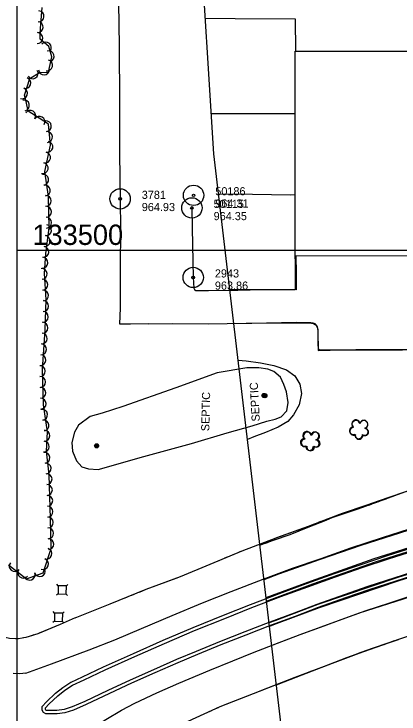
# Model space of a CAD drawing. Extents: x 353423 to 364002, y 127000 to 201942.
# Drawn here: x 359998 to 360282, y 133158 to 133674 of the extents above; entities that cross this region are included whole.
import ezdxf

# ---------------------------------------------------------------- set-up
doc = ezdxf.new("R2010")
doc.units = 0
for name, color, linetype in [('E_DTM_SlopeTop', 7, 'Continuous'), ('E_FEN_Generic', 7, 'Continuous'), ('E_LAND_TreeLine', 7, 'Continuous'), ('E_MISCPROP', 7, 'Continuous'), ('E_RDWY_AsphConc', 7, 'Continuous'), ('E_RDWY_Gravel', 7, 'Continuous'), ('E_SGN', 7, 'Continuous'), ('E_STRUCT_WingWall', 7, 'Continuous'), ('E_UTL_ETransformer', 7, 'Continuous'), ('E_WTR_FlowLine', 7, 'Continuous')]:
    doc.layers.add(name, color=color, linetype=linetype)

msp = doc.modelspace()

# ---------------------------------------------------------------- linework, layer by layer
at = {"layer": 'E_DTM_SlopeTop'}
for points in [[(360182.12, 133256.96), (360192.85, 133261.23), (360223.69, 133272.01), (360253.77, 133282.21), (360288.47, 133293.44), (360326.84, 133305.23), (360357.9, 133313.97), (360390.26, 133322.54), (360421.44, 133330.15), (360456.51, 133337.86), (360490.45, 133344.97), (360520.11, 133351.38), (360526.85, 133354.04), (360530.53, 133357.19), (360539.85, 133363.92), (360547.02, 133368.71), (360550.06, 133372.44), (360551.65, 133376.4), (360553.23, 133383.39), (360555.89, 133430.41), (360555.81, 133481.76), (360555.33, 133565.87), (360555.51, 133660.84), (360555.37, 133755.07)], [(360128.86, 133531.05), (360129.08, 133516.28), (360129.63, 133491.43), (360129.78, 133479.76), (360130.16, 133471.75), (360130.71, 133470.77), (360131.62, 133470.21), (360141.06, 133470.2), (360162.72, 133470.44), (360181.1, 133470.82), (360204.94, 133471.01), (360205.25, 133471.93), (360205.33, 133481.18), (360205.17, 133491.08), (360205.14, 133495.5)], [(360006.29, 133187.84), (360025.26, 133194.79), (360052.98, 133205.1), (360071.85, 133212.44), (360091.53, 133220.77), (360114.27, 133230.3), (360136.54, 133239.67), (360157.72, 133248.11), (360181.38, 133257.23), (360202.94, 133265.29), (360224.09, 133272.51), (360246, 133280.32), (360269.41, 133287.87), (360289.47, 133294.36), (360314.09, 133301.78), (360333.1, 133307.44), (360354.51, 133313.55), (360373.78, 133318.45), (360400.17, 133325.29), (360427.85, 133331.85), (360453.76, 133337.85), (360478.53, 133342.83), (360499.94, 133347.22), (360523.7, 133352.98)], [(360589.7, 133314.3), (360545.54, 133307.42), (360507.24, 133300.53), (360457.59, 133289.96), (360418.36, 133280.97), (360373.04, 133269.25), (360336.05, 133258.69), (360290.01, 133244.21), (360252.17, 133232.01), (360208.39, 133216.08), (360187.87, 133208.16)], [(360183.69, 133243.58), (360217.12, 133255.99), (360263.43, 133272.4), (360311.1, 133287.46)], [(360183.99, 133241.03), (360217.97, 133253.64), (360264.23, 133270.03), (360311.83, 133285.06)], [(360048.16, 133185.18), (360063.68, 133192.49), (360085.62, 133202.44), (360107.65, 133212.12), (360129.82, 133221.52), (360152.13, 133230.53), (360172.18, 133238.56), (360193.58, 133246.71), (360213.43, 133253.97), (360233.99, 133261.3), (360253.68, 133268.06), (360273.18, 133274.61), (360287.89, 133279.27)], [(360049.22, 133182.92), (360064.73, 133190.22), (360086.64, 133200.16), (360108.64, 133209.83), (360130.77, 133219.21), (360153.06, 133228.21), (360173.09, 133236.23), (360194.46, 133244.37), (360214.28, 133251.62), (360234.82, 133258.94), (360254.48, 133265.69), (360273.95, 133272.23), (360288.64, 133276.88)], [(360338.92, 133276.37), (360280.78, 133258.43), (360221.84, 133238.4), (360190.01, 133226.54), (360185.89, 133224.91)], [(360339.61, 133273.97), (360281.55, 133256.05), (360222.68, 133236.05), (360190.9, 133224.2), (360186.2, 133222.34)], [(360297.01, 133261.39), (360279.3, 133255.81), (360259.36, 133249.41), (360242.08, 133243.3), (360221.97, 133236.19), (360205.07, 133229.68), (360187.2, 133223.2), (360168.68, 133215.98), (360150.18, 133208.68), (360132.89, 133201.57), (360118.38, 133195.54), (360101.55, 133188.14), (360084.2, 133180.38), (360067.91, 133172.85), (360050.88, 133164.62), (360041.39, 133160.54), (360035.04, 133158.61), (360029.37, 133157.92), (360022.49, 133157.84), (360021.01, 133157.88), (360019.2, 133158.79), (360018.29, 133160.45), (360018.36, 133163.29), (360021.5, 133166.62), (360028.28, 133173.1), (360033.56, 133177.33), (360039.45, 133181.1)], [(360296.26, 133263.78), (360278.54, 133258.2), (360258.56, 133251.78), (360241.25, 133245.66), (360221.1, 133238.54), (360204.2, 133232.03), (360186.32, 133225.54), (360167.77, 133218.31), (360149.24, 133211), (360131.94, 133203.88), (360117.4, 133197.84), (360100.53, 133190.42), (360083.16, 133182.66), (360066.85, 133175.11), (360049.84, 133166.89), (360040.53, 133162.89), (360034.53, 133161.07), (360029.2, 133160.42), (360022.51, 133160.34), (360021.63, 133160.36), (360021.02, 133160.67), (360020.81, 133161.06), (360020.84, 133162.27), (360023.28, 133164.86), (360029.92, 133171.22), (360035.02, 133175.3), (360040.79, 133179)], [(360076.88, 133160.45), (360086.72, 133165.72), (360102.95, 133173.41), (360119.06, 133180.57), (360141.94, 133190.03), (360159.08, 133196.98), (360174.81, 133203.33), (360191.95, 133209.89), (360208.75, 133216.28), (360223.61, 133221.86), (360239.68, 133227.59), (360257.45, 133233.96), (360274.1, 133239.6), (360292.65, 133245.74)], [(360006.29, 133187.84), (360001.88, 133187.31), (359997.03, 133187.56)], [(360039.66, 133181.22), (360048.16, 133185.19)], [(360040.71, 133178.95), (360049.22, 133182.92)], [(360048.78, 132621.5), (360048.89, 132669.64), (360049.35, 132727.67), (360049.55, 132793.59), (360049.56, 132842.31), (360049.06, 132893.44), (360046.96, 132939.69), (360042.98, 132986.33), (360039.67, 133020.54), (360037.17, 133037.76), (360034.31, 133052.24), (360029.63, 133066.98), (360021.41, 133087.08), (360018.16, 133096.99), (360017.7, 133101.52), (360017.78, 133107.23), (360018.75, 133112.13), (360021.8, 133117.95), (360028.18, 133126.37), (360033.76, 133132.81), (360043.26, 133140.02), (360051.73, 133145.18), (360065.4, 133153.61), (360076.88, 133160.45)]]:
    msp.add_lwpolyline(points, dxfattribs=at)
at = {"layer": 'E_FEN_Generic'}
for points in [[(360023.51, 133516.3), (360023.03, 133539.52), (360020.34, 133557.82), (360024.58, 133577.27), (360023.05, 133592.9), (360016.13, 133597.27), (360007.97, 133602.47), (360006.49, 133609.49), (360005.25, 133614.26), (360009.3, 133626.61), (360016.25, 133630.93), (360023.1, 133631.24), (360025.57, 133642.42), (360023.26, 133650.2), (360016.84, 133655.65), (360017.12, 133663.42), (360018.26, 133679.03)], [(359993.54, 133267.74), (360006.67, 133257.42), (360018.96, 133261.79), (360025.04, 133279.74), (360024.57, 133301.97), (360023.6, 133334.04), (360021.52, 133351.55), (360022.19, 133365.95), (360019.31, 133385.68), (360018.66, 133411.81), (360020.6, 133441.03), (360021.33, 133463.41), (360020.05, 133482.68), (360021.15, 133497.42), (360023.51, 133516.29)]]:
    msp.add_lwpolyline(points, dxfattribs=at)
for centre, radius, start, end in [((360015.68, 133672.43), 4, 265.8265, 85.8112), ((360015.1, 133664.45), 4, 265.8265, 85.8112), ((360014.77, 133656.38), 4, 267.9556, 87.9403), ((360021.08, 133649.3), 4, 319.6336, 139.6183), ((360023.22, 133642.97), 4, 286.559, 106.5437), ((360022.06, 133636.22), 4, 257.5917, 77.5764), ((360011.33, 133630.33), 4, 211.8706, 31.8553), ((360019.66, 133633.18), 4, 182.5959, 2.5806), ((360005.97, 133623.16), 4, 251.8341, 71.8188), ((360003.48, 133615.56), 4, 251.8341, 71.8188), ((360004.93, 133606.72), 4, 281.898, 101.8827), ((360009.55, 133598.98), 4, 327.4836, 147.4683), ((360016.31, 133594.68), 4, 327.7358, 147.7205), ((360021.1, 133591.35), 4, 275.6048, 95.5895), ((360021.88, 133583.39), 4, 275.6048, 95.5895), ((360022.19, 133576.11), 4, 257.6917, 77.6764), ((360020.48, 133568.3), 4, 257.6917, 77.6764), ((360018.77, 133560.48), 4, 257.6917, 77.6764), ((360019.1, 133551.85), 4, 278.3724, 98.357), ((360020.26, 133543.93), 4, 278.3724, 98.357), ((360021, 133536.25), 4, 271.1997, 91.1844), ((360021.17, 133528.25), 4, 271.1997, 91.1844), ((360021.33, 133520.25), 4, 271.1997, 91.1844), ((360021.19, 133514.63), 4, 262.8788, 82.8634), ((360020.2, 133506.69), 4, 262.8788, 82.8634), ((360019.21, 133498.75), 4, 262.8788, 82.8634), ((360018.55, 133490.68), 4, 265.7322, 85.7169), ((360017.97, 133482.41), 4, 273.806, 93.7907), ((360018.5, 133474.43), 4, 273.806, 93.7907), ((360019.03, 133466.44), 4, 273.806, 93.7907), ((360019.08, 133458.66), 4, 268.1534, 88.1381), ((360018.82, 133450.67), 4, 268.1534, 88.1381), ((360018.56, 133442.67), 4, 268.1534, 88.1381), ((360018.09, 133434.76), 4, 266.2005, 86.1852), ((360017.56, 133426.78), 4, 266.2005, 86.1852), ((360017.03, 133418.8), 4, 266.2005, 86.1852), ((360016.59, 133410.62), 4, 271.4384, 91.423), ((360016.79, 133402.62), 4, 271.4384, 91.423), ((360016.99, 133394.63), 4, 271.4384, 91.423), ((360017.19, 133386.63), 4, 271.4384, 91.423), ((360018.25, 133378.46), 4, 278.3235, 98.3082), ((360019.41, 133370.54), 4, 278.3235, 98.3082), ((360249.85, 133371.69), 2.97, 7.0637, 228.2976), ((360249.92, 133371.25), 2.97, 8.7472, 229.9811), ((360255.7, 133371.44), 2.97, 284.7145, 167.6878), ((360255.78, 133371.17), 2.97, 286.3981, 169.3713), ((360247.87, 133366.69), 2.78, 90.0346, 297.8076), ((360248.09, 133366.2), 2.78, 91.7181, 299.4911), ((360256.33, 133365.95), 2.61, 229.4197, 87.3523), ((360019.96, 133363), 4, 267.3368, 87.3215), ((360213.65, 133363.08), 2.97, 7.0637, 228.2976), ((360214.14, 133362.77), 2.97, 8.7472, 229.9811), ((360219.5, 133362.83), 2.97, 284.7145, 167.6878), ((360220, 133362.69), 2.97, 286.3981, 169.3713), ((360251.87, 133363.6), 2.78, 166.7116, 7.7226), ((360252.19, 133363.22), 2.78, 168.3952, 9.4062), ((360256.57, 133365.71), 2.61, 231.1033, 89.0359), ((360019.59, 133355.01), 4, 267.3368, 87.3215), ((360211.68, 133358.08), 2.78, 90.0346, 297.8076), ((360212.31, 133357.72), 2.78, 91.7181, 299.4911), ((360220.14, 133357.34), 2.61, 229.4197, 87.3523), ((360220.79, 133357.23), 2.61, 231.1033, 89.0359), ((360215.68, 133354.99), 2.78, 166.7116, 7.7226), ((360216.41, 133354.74), 2.78, 168.3952, 9.4062), ((360019.99, 133346.7), 4, 276.7618, 96.7465), ((360020.93, 133338.76), 4, 276.7618, 96.7465), ((360021.59, 133330.98), 4, 271.7478, 91.7325), ((360021.84, 133322.98), 4, 271.7478, 91.7325), ((360022.08, 133314.99), 4, 271.7478, 91.7325), ((360022.32, 133306.99), 4, 271.7478, 91.7325), ((360022.54, 133299.01), 4, 271.2073, 91.1919), ((360022.7, 133291.02), 4, 271.2073, 91.1919), ((360022.87, 133283.02), 4, 271.2073, 91.1919), ((360021.55, 133275.98), 4, 251.3158, 71.3005), ((360018.99, 133268.41), 4, 251.3158, 71.3005), ((359998, 133266.89), 4, 141.8607, 321.8454), ((360004.29, 133261.95), 4, 141.8607, 321.8454), ((360009.1, 133260.5), 4, 199.5775, 19.5622), ((360016.64, 133263.18), 4, 199.5775, 19.5622)]:
    msp.add_arc(centre, radius, start, end, dxfattribs=at)
at = {"layer": 'E_LAND_TreeLine'}
for p, q in [((360000, 132500), (360000, 135000)), ((360000, 131000), (360000, 133500)), ((360000, 133500), (364000, 133500)), ((360000, 133500), (364000, 133500))]:
    msp.add_line(p, q, dxfattribs=at)
at = {"layer": 'E_MISCPROP'}
for points in [[(360076.29, 133515.44), (360076.04, 133537.05), (360075.67, 133571.09), (360075.65, 133609.43), (360075.36, 133650.47), (360074.82, 133682.4), (360074.7, 133693.21), (360074.7, 133694.46), (360075.08, 133695.05), (360076.77, 133695.15), (360094.36, 133695.31), (360113.03, 133695.38)], [(360138.82, 133671.12), (360160.71, 133670.92), (360204.94, 133670.55), (360205.15, 133646.72)], [(360205.06, 133600.38), (360163.11, 133600.46), (360143.25, 133600.38)], [(360148.6, 133541.27), (360159.23, 133541.56), (360201.75, 133540.83), (360205.03, 133540.87)], [(360097.14, 133445.68), (360083.46, 133445.31), (360075.63, 133445.28), (360076.12, 133457.4), (360076.18, 133486.83), (360076.29, 133515.44)], [(360205.57, 133495.65), (360205.83, 133483.01), (360205.82, 133470.66), (360167.88, 133470.77), (360156.93, 133470.6)], [(360097.14, 133445.68), (360114.62, 133445.91), (360140.88, 133445.57), (360168.91, 133446.05), (360192.71, 133446.23), (360215.48, 133446.3), (360218.5, 133445.8), (360219.77, 133445.02), (360220.86, 133444.06), (360221.53, 133442.3), (360221.83, 133439.97), (360222.03, 133425.95), (360239.73, 133426.32), (360261.64, 133426.37), (360284.26, 133426.3)], [(360322.23, 133426.3), (360249.85, 133426.37), (360225.56, 133426.17), (360223.51, 133426.15), (360222.58, 133426.58), (360222.17, 133427.42), (360222.05, 133430.63), (360222.07, 133438.66), (360222.02, 133441.06), (360221.23, 133443.76), (360219.81, 133445.56), (360218.41, 133446.12), (360216.69, 133446.27), (360214.77, 133446.33), (360205.64, 133446.54), (360173.05, 133445.8), (360159.88, 133445.55)]]:
    msp.add_lwpolyline(points, dxfattribs=at)
at = {"layer": 'E_RDWY_AsphConc'}
for centre, radius in [((360075.83, 133537.73), 7.5), ((360075.83, 133537.73), 7.5), ((360075.83, 133537.73), 7.5), ((360130.09, 133540.37), 7.5), ((360130.09, 133540.37), 7.5), ((360130.09, 133540.37), 7.5), ((360130.09, 133540.37), 0.96), ((360130.09, 133540.37), 0.96), ((360130.09, 133540.37), 0.96), ((360075.83, 133537.73), 0.96), ((360075.83, 133537.73), 0.96), ((360075.83, 133537.73), 0.96), ((360128.86, 133531.05), 7.5), ((360128.86, 133531.05), 7.5), ((360128.86, 133531.05), 7.5), ((360128.86, 133531.05), 0.96), ((360128.86, 133531.05), 0.96), ((360128.86, 133531.05), 0.96), ((360129.78, 133479.76), 7.5), ((360129.78, 133479.76), 7.5), ((360129.78, 133479.76), 7.5), ((360129.78, 133479.76), 0.96), ((360129.78, 133479.76), 0.96), ((360129.78, 133479.76), 0.96)]:
    msp.add_circle(centre, radius, dxfattribs=at)
at = {"layer": 'E_RDWY_Gravel'}
msp.add_lwpolyline([(360226.78, 132878.09), (360145.09, 133571.05), (360081.63, 134583.34)], dxfattribs=at)
at = {"layer": 'E_SGN'}
for p, q in [((360030.18, 133252.32), (360029.15, 133253.41)), ((360037.27, 133253.21), (360036.18, 133252.18)), ((360030.04, 133246.32), (360028.95, 133245.29)), ((360037.07, 133245.09), (360036.04, 133246.18)), ((360027.48, 133232.22), (360026.45, 133233.31)), ((360034.57, 133233.12), (360033.48, 133232.08)), ((360027.34, 133226.22), (360026.26, 133225.19)), ((360034.38, 133225), (360033.34, 133226.08))]:
    msp.add_line(p, q, dxfattribs=at)
for points in [[(360036.04, 133246.18), (360036.18, 133252.18), (360030.18, 133252.32), (360030.04, 133246.32)], [(360033.34, 133226.08), (360033.48, 133232.08), (360027.48, 133232.22), (360027.34, 133226.22)]]:
    msp.add_lwpolyline(points, close=True, dxfattribs=at)
at = {"layer": 'E_STRUCT_WingWall'}
for points in [[(360304.14, 133327.41), (360300.14, 133326.47), (360282.9, 133320.38), (360276.33, 133317.9)], [(360266.61, 133315.02), (360285.27, 133321.36), (360294.13, 133324.15)], [(360042.77, 133228.56), (360068.52, 133239.01), (360095.12, 133249.76), (360120.29, 133259.24), (360142.31, 133268.3), (360165.84, 133278.14), (360190.94, 133287.65), (360214.84, 133296.41), (360237.92, 133305.08), (360258.86, 133312.38), (360285.27, 133321.36)], [(360282.9, 133320.38), (360266.3, 133314.12), (360249.67, 133308.38), (360232.04, 133302.34), (360214.48, 133295.35), (360200.99, 133290.02), (360188.86, 133285.69), (360179.14, 133282.22)], [(360239.21, 133305.53), (360258.86, 133312.38), (360266.61, 133315.02)], [(360261.09, 133312.33), (360259.17, 133311.66)], [(360266.83, 133314.33), (360266.3, 133314.12), (360264.92, 133313.65)], [(360272.53, 133316.47), (360270.63, 133315.76)], [(360255.34, 133310.34), (360249.67, 133308.38), (360232.04, 133302.34), (360227.6, 133300.57)], [(360227.96, 133301.34), (360229.83, 133302.05)], [(360233.58, 133303.45), (360235.45, 133304.16)], [(360191.38, 133287.82), (360214.84, 133296.41), (360218.6, 133297.83)], [(360227.6, 133300.57), (360214.48, 133295.35), (360200.99, 133290.02), (360200.24, 133289.76)], [(360222.34, 133299.23), (360224.22, 133299.94)], [(360164.29, 133277.49), (360165.84, 133278.14), (360190.94, 133287.65), (360191.38, 133287.82)], [(360190.69, 133286.34), (360188.86, 133285.69), (360188.78, 133285.66)], [(360196.42, 133288.39), (360194.51, 133287.71)], [(360036.36, 133104.77), (360045.69, 133114.1), (360058.06, 133121.63), (360077.94, 133132.55), (360095.72, 133140.96), (360126.12, 133152.35), (360149.6, 133163.2), (360178.68, 133174.55), (360205.12, 133184.78), (360240.39, 133198.28), (360262.78, 133206.61), (360296.82, 133217.99), (360317.55, 133225.39), (360343.72, 133233.38), (360370.17, 133241.22), (360404.55, 133250.27), (360428.05, 133255.92), (360457.14, 133261.65), (360482.65, 133266.99), (360508.44, 133271.29), (360539.45, 133277.74), (360546.12, 133278.91), (360556.89, 133280.01), (360573.39, 133280.97)], [(360179.23, 133282.26), (360179.14, 133282.22)], [(360184.96, 133284.3), (360183.05, 133283.62)], [(360191.28, 133179.23), (360201.24, 133183.17), (360243.14, 133199.29), (360282.25, 133213.29), (360325.88, 133227.73), (360364.9, 133239.06), (360408.32, 133250.57), (360444.21, 133258.9), (360482.71, 133267.76), (360514.55, 133273.07), (360545.36, 133278.43), (360547.6, 133279.62), (360546.01, 133285.42)], [(360158.75, 133275.17), (360160.6, 133275.94)], [(360147.68, 133270.54), (360149.52, 133271.31)], [(360153.21, 133272.86), (360155.06, 133273.63)], [(360117.14, 133258.05), (360120.29, 133259.24), (360142.31, 133268.3), (360143.99, 133269)], [(360090.04, 133247.71), (360095.12, 133249.76), (360117.14, 133258.05)], [(360084.48, 133245.46), (360086.34, 133246.21)], [(360042.77, 133228.56), (360068.52, 133239.01), (360069.65, 133239.46)], [(360073.36, 133240.96), (360075.21, 133241.71)], [(360078.92, 133243.21), (360080.77, 133243.96)], [(360042.77, 133228.56), (360031.61, 133223.68), (360015.23, 133216.96), (360006.26, 133214.2), (360000.95, 133213.24), (359994.23, 133213.36), (359987.75, 133214.9), (359981.89, 133217.15), (359975.85, 133221.72), (359972.32, 133224.59)], [(360042.77, 133228.56), (360031.61, 133223.68), (360016.05, 133217.3)], [(360006.52, 133214.28), (360006.26, 133214.2), (360004.56, 133213.89)], [(360012.26, 133216.05), (360010.35, 133215.46)], [(360000.62, 133213.25), (359998.62, 133213.28)], [(360253.81, 133203.27), (360262.78, 133206.61), (360281.21, 133212.77)], [(360270.58, 133209.11), (360272.5, 133209.8)], [(360276.34, 133211.17), (360278.26, 133211.86)], [(360226.68, 133193.03), (360240.39, 133198.28), (360253.81, 133203.27)], [(360238.97, 133197.69), (360243.14, 133199.29), (360266.75, 133207.74)], [(360211.4, 133187.08), (360238.97, 133197.69)], [(360215.47, 133188.74), (360217.34, 133189.46)], [(360221.07, 133190.89), (360222.94, 133191.6)], [(360179.08, 133174.7), (360205.12, 133184.78), (360206.13, 133185.17)], [(360199.99, 133182.68), (360201.24, 133183.17), (360201.89, 133183.42)], [(360205.69, 133184.89), (360207.59, 133185.62)], [(360209.86, 133186.6), (360211.73, 133187.31)], [(360194.31, 133180.43), (360196.21, 133181.18)], [(360152.07, 133164.16), (360178.68, 133174.55), (360179.08, 133174.7)], [(360146.56, 133161.79), (360148.37, 133162.63)], [(360141.11, 133159.27), (360142.93, 133160.11)]]:
    msp.add_lwpolyline(points, dxfattribs=at)
at = {"layer": 'E_UTL_ETransformer'}
msp.add_lwpolyline([(360163.04, 133418.74), (360168.83, 133418.26), (360179.38, 133416.78), (360189.29, 133414.71), (360198.52, 133411.56), (360204.79, 133407.21), (360208.45, 133400.93), (360209.71, 133394.19), (360208.05, 133385.81), (360203.73, 133378.53), (360199.51, 133373.49), (360192.55, 133369.21), (360183.09, 133365.3), (360174.64, 133362.09), (360169.95, 133360.13)], dxfattribs=at)
for centre, radius in [((360181.99, 133392.66), 1.5), ((360181.99, 133392.67), 1.22), ((360182.01, 133392.66), 0.968), ((360182.72, 133392.57), 1.5), ((360182.01, 133392.63), 0.605), ((360182.73, 133392.58), 1.22), ((360182.74, 133392.57), 0.968), ((360182.75, 133392.54), 0.605), ((360058.51, 133355.57), 1.5), ((360058.51, 133355.58), 1.22), ((360058.52, 133355.57), 0.968), ((360058.53, 133355.54), 0.605)]:
    msp.add_circle(centre, radius, dxfattribs=at)
at = {"layer": 'E_WTR_FlowLine'}
msp.add_lwpolyline([(360205.09, 133646.72), (360374.95, 133646.62), (360374.89, 133541.31), (360420.12, 133541.28), (360420.11, 133516.63), (360428.72, 133516.62), (360428.71, 133499.11), (360420.54, 133499.11), (360420.53, 133478.03), (360374.46, 133478.05), (360374.47, 133495.55), (360205, 133495.65)], close=True, dxfattribs=at)
msp.add_lwpolyline([(360154.81, 133365.04), (360173.18, 133370.32), (360184.23, 133373.82), (360190.31, 133375.35), (360194.69, 133376.96), (360198.99, 133381.38), (360199.89, 133387.46), (360198.6, 133395.3), (360196.78, 133400.92), (360194.14, 133406.13), (360189.2, 133410.49), (360184.8, 133412.21), (360178.2, 133412.99), (360169.43, 133413.01), (360147.52, 133409.34), (360116.95, 133398.24), (360077.74, 133384.55), (360062.57, 133379.71), (360053.7, 133377.21), (360045.07, 133370.89), (360042.23, 133365.76), (360040.33, 133358.04), (360040.79, 133351.55), (360043.63, 133344.38), (360047.72, 133340.14), (360052.64, 133338.49), (360059.54, 133338.19), (360093.4, 133347.58), (360128.51, 133357.18), (360154.81, 133365.04)], dxfattribs=at)

# ---------------------------------------------------------------- texts
at = {"layer": 'E_LAND_TreeLine'}
msp.add_text('  133500  ', height=15, dxfattribs=at).set_placement((360000, 133503.75))
at = {"layer": 'E_RDWY_AsphConc'}
for s, p in [('50186', (360146.09, 133540.37)), ('50186', (360146.09, 133540.37)), ('50186', (360146.09, 133540.37)), ('3781', (360091.83, 133537.73)), ('3781', (360091.83, 133537.73)), ('3781', (360091.83, 133537.73)), ('964.93', (360091.83, 133528.73)), ('964.93', (360091.83, 133528.73)), ('964.93', (360091.83, 133528.73)), ('50115', (360144.86, 133531.05)), ('50115', (360144.86, 133531.05)), ('50115', (360144.86, 133531.05)), ('964.31', (360146.09, 133531.37)), ('964.31', (360146.09, 133531.37)), ('964.31', (360146.09, 133531.37)), ('964.35', (360144.86, 133522.05)), ('964.35', (360144.86, 133522.05)), ('964.35', (360144.86, 133522.05)), ('2943', (360145.78, 133479.76)), ('2943', (360145.78, 133479.76)), ('2943', (360145.78, 133479.76)), ('963.86', (360145.78, 133470.76)), ('963.86', (360145.78, 133470.76)), ('963.86', (360145.78, 133470.76))]:
    msp.add_text(s, height=6, dxfattribs=at).set_placement(p)
at = {"layer": 'E_UTL_ETransformer'}
for rotation, p in [(93.0278, (360178.97, 133373.64)), (88.64, (360141.62, 133366.27))]:
    msp.add_text('SEPTIC', height=6, rotation=rotation, dxfattribs=at).set_placement(p)

doc.saveas('drawing.dxf')
